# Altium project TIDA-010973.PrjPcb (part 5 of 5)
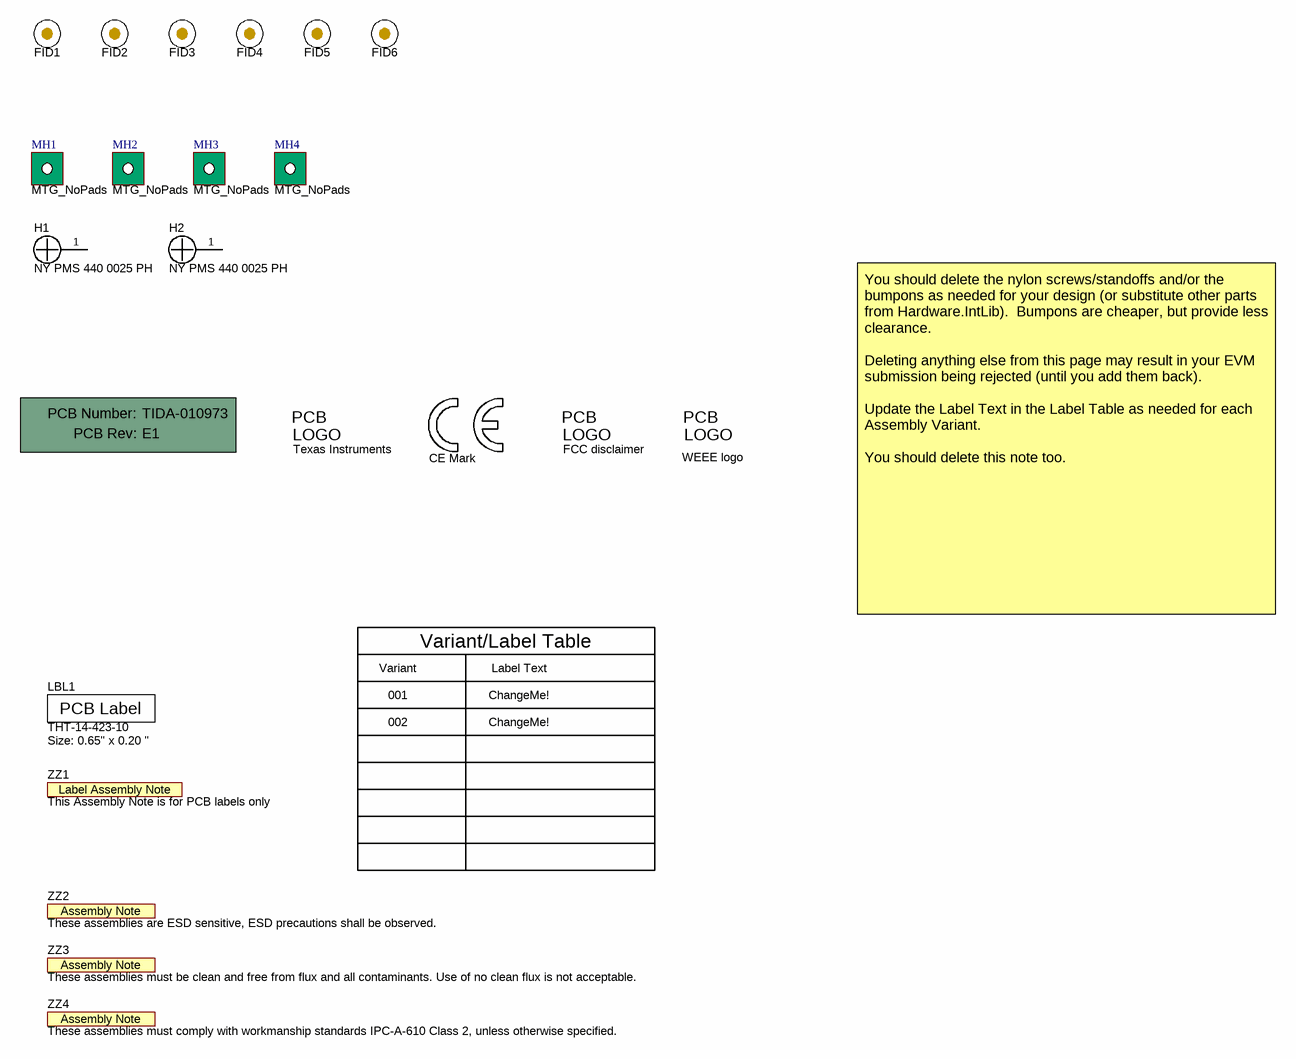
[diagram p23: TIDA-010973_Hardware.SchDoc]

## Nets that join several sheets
5V: TIDA-010973_HostPortInterface (J11.2 J11.4), TIDA-010973_SOM_PMIC (10 pins), TIDA-010973_SystemPower (16 pins), TIDA-010973_USB2 (C135.2 C136.1 U38.5)
GND: TIDA-010973_EthernetConnector (16 pins), TIDA-010973_HostPortInterface (49 pins), TIDA-010973_SOM-Memory (15 pins), SOM/SOM-ETH1 (21 pins), TIDA-010973_SOM_PMIC (159 pins), TIDA-010973_SOM_MCU (64 pins), SOM/SOM-ETH2 (21 pins), TIDA-010973_SystemPower (37 pins), TIDA-010973_SystemLED (38 pins), TIDA-010973_USB2 (40 pins), TIDA-010973_JTAG_UART (17 pins), TIDA-010973_Memory (9 pins), TIDA-010973_BootConfig (22 pins)
VDDA_AM261_1V8_LDO: TIDA-010973_SOM_PMIC (10 pins), TIDA-010973_SOM_MCU (C216.1 C217.2 U2.U15)
VSYS_1V8: TIDA-010973_HostPortInterface (C218.2 J12.3 U55.1 U55.5), TIDA-010973_SOM-Memory (19 pins), TIDA-010973_SOM_PMIC (11 pins), TIDA-010973_SOM_MCU (7 pins), TIDA-010973_Memory (18 pins)
VSYS_3V3: TIDA-010973_EthernetConnector (R84.2 R85.2 R86.2 R87.2), TIDA-010973_HostPortInterface (29 pins), TIDA-010973_SOM-Memory (C86.1 R55.2 U11.8), SOM/SOM-ETH1 (12 pins), TIDA-010973_SOM_PMIC (37 pins), TIDA-010973_SOM_MCU (29 pins), SOM/SOM-ETH2 (12 pins), TIDA-010973_SystemLED (34 pins), TIDA-010973_USB2 (R133.2 R141.1 U34.3), TIDA-010973_JTAG_UART (14 pins), TIDA-010973_BootConfig (19 pins)
VSYS_USB_5V: TIDA-010973_SystemPower (7 pins), TIDA-010973_USB2 (C131.2 C133.1 U37.7 U37.8)
~{ETH0_PHY_INT}: SOM/SOM-ETH1 (R27_SOM-ETH1.2 U9_SOM-ETH1.21), TIDA-010973_SOM_MCU (U2.B4)
~{ETH1_PHY_INT}: TIDA-010973_SOM_MCU (U2.A10), SOM/SOM-ETH2 (R27_SOM-ETH2.2 U9_SOM-ETH2.21)
~{PHY_RESET}: SOM/SOM-ETH1 (U9_SOM-ETH1.32), TIDA-010973_SOM_MCU (U3.7)
~{PHY_RESET}: TIDA-010973_SOM_MCU (U3.3), SOM/SOM-ETH2 (U9_SOM-ETH2.32)
AM261_I2C0.SCL: TIDA-010973_SOM-Memory (U11.6), TIDA-010973_SOM_PMIC (U1.14), TIDA-010973_SOM_MCU (R219.1 U2.A15 U7.12 U8.4), TIDA-010973_SystemLED (U21.4)
AM261_I2C0.SDA: TIDA-010973_SOM-Memory (U11.5), TIDA-010973_SOM_PMIC (U1.13), TIDA-010973_SOM_MCU (R17.1 U2.B15 U7.13 U8.3), TIDA-010973_SystemLED (U21.5)
AM261_PORZN: TIDA-010973_SOM_MCU (6 pins), TIDA-010973_BootConfig (R122.1)
AM261_SAFETY_ERR: TIDA-010973_SOM_MCU (U2.E3), TIDA-010973_SystemLED (Q13.1 R213.1)
AM261_SOP0: TIDA-010973_SOM_MCU (R16.1), TIDA-010973_BootConfig (U32.15)
AM261_SOP1: TIDA-010973_SOM_MCU (R120.1), TIDA-010973_BootConfig (U32.14)
AM261_SOP2: TIDA-010973_SOM_MCU (R121.1), TIDA-010973_BootConfig (U32.13)
AM261_SOP3: TIDA-010973_SOM_MCU (R123.1), TIDA-010973_BootConfig (U32.12)
AM261_TCK: TIDA-010973_SOM_MCU (U2.D4), TIDA-010973_JTAG_UART (R239.1 U51.2)
AM261_TDI: TIDA-010973_SOM_MCU (U2.C5), TIDA-010973_JTAG_UART (R240.1 U51.5)
AM261_TDO: TIDA-010973_SOM_MCU (R212.1), TIDA-010973_JTAG_UART (R241.1 U51.7)
AM261_TMS: TIDA-010973_SOM_MCU (U2.D6), TIDA-010973_JTAG_UART (R242.1 U51.10)
AM261_UART0_RXD: TIDA-010973_SOM_MCU (U2.A8), TIDA-010973_JTAG_UART (R226.1)
AM261_UART0_TXD: TIDA-010973_SOM_MCU (R218.1), TIDA-010973_JTAG_UART (U43.3)
AM261_USB0_D_N: TIDA-010973_SOM_MCU (U2.W1), TIDA-010973_USB2 (U34.8)
AM261_USB0_D_P: TIDA-010973_SOM_MCU (U2.V1), TIDA-010973_USB2 (U34.10)
AM261_USB0_DRVVBUS: TIDA-010973_SOM_MCU (U2.U2), TIDA-010973_USB2 (R142.1 U38.4)
AM261_USB0_MUX_SEL: TIDA-010973_SOM_MCU (U7.8), TIDA-010973_USB2 (R134.1 U34.11)
AM261_USB0_VBUS_OC: TIDA-010973_SOM_MCU (U2.F2), TIDA-010973_USB2 (R141.2 U38.3)
AM261_WARMRSTN: TIDA-010973_SOM_MCU (U2.G3 U4.2 U29.2 U47.2), TIDA-010973_BootConfig (Q14.1 R214.1 R215.2)
CLK_25M: SOM/SOM-ETH1 (U9_SOM-ETH1.9), TIDA-010973_SOM_MCU (R19.2)
CLK_25M: TIDA-010973_SOM_MCU (R18.2), SOM/SOM-ETH2 (U9_SOM-ETH2.9)
COL: SOM/SOM-ETH1 (U9_SOM-ETH1.28), TIDA-010973_SOM_MCU (U2.J19)
COL: TIDA-010973_SOM_MCU (U2.E20), SOM/SOM-ETH2 (U9_SOM-ETH2.28)
CRS: SOM/SOM-ETH1 (R30_SOM-ETH1.2 U9_SOM-ETH1.29), TIDA-010973_SOM_MCU (U2.J20)
CRS: TIDA-010973_SOM_MCU (U2.E19), SOM/SOM-ETH2 (R30_SOM-ETH2.2 U9_SOM-ETH2.29)
ETH0_LED_ACT: TIDA-010973_EthernetConnector (Q7.1), SOM/SOM-ETH1 (R29_SOM-ETH1.2 U9_SOM-ETH1.30)
ETH0_LED_LINK: TIDA-010973_EthernetConnector (Q5.1), SOM/SOM-ETH1 (R28_SOM-ETH1.1 R201_SOM-ETH1.2 U9_SOM-ETH1.31), TIDA-010973_SOM_MCU (U2.J18)
ETH0_RD_N: TIDA-010973_EthernetConnector (J2.3 U17.5), SOM/SOM-ETH1 (C78_SOM-ETH1.1 U9_SOM-ETH1.4)
ETH0_RD_P: TIDA-010973_EthernetConnector (J2.5 U17.1), SOM/SOM-ETH1 (C77_SOM-ETH1.1 U9_SOM-ETH1.5)
ETH0_TD_N: TIDA-010973_EthernetConnector (J2.6 U17.3), SOM/SOM-ETH1 (C80_SOM-ETH1.1 U9_SOM-ETH1.6)
ETH0_TD_P: TIDA-010973_EthernetConnector (J2.8 U17.4), SOM/SOM-ETH1 (C79_SOM-ETH1.1 U9_SOM-ETH1.7)
ETH1_LED_ACT: TIDA-010973_EthernetConnector (Q8.1), SOM/SOM-ETH2 (R29_SOM-ETH2.2 U9_SOM-ETH2.30)
ETH1_LED_LINK: TIDA-010973_EthernetConnector (Q6.1), TIDA-010973_SOM_MCU (U2.G18), SOM/SOM-ETH2 (R28_SOM-ETH2.1 R201_SOM-ETH2.2 U9_SOM-ETH2.31)
ETH1_RD_N: TIDA-010973_EthernetConnector (J3.3 U57.5), SOM/SOM-ETH2 (C78_SOM-ETH2.1 U9_SOM-ETH2.4)
ETH1_RD_P: TIDA-010973_EthernetConnector (J3.5 U57.1), SOM/SOM-ETH2 (C77_SOM-ETH2.1 U9_SOM-ETH2.5)
ETH1_TD_N: TIDA-010973_EthernetConnector (J3.6 U57.3), SOM/SOM-ETH2 (C80_SOM-ETH2.1 U9_SOM-ETH2.6)
ETH1_TD_P: TIDA-010973_EthernetConnector (J3.8 U57.4), SOM/SOM-ETH2 (C79_SOM-ETH2.1 U9_SOM-ETH2.7)
HPI_IRQ0: TIDA-010973_HostPortInterface (J11.26), TIDA-010973_SOM_MCU (U2.T1)
HPI_IRQ1: TIDA-010973_HostPortInterface (J11.27), TIDA-010973_SOM_MCU (U2.U1)
HPI_IRQ2: TIDA-010973_HostPortInterface (J11.28), TIDA-010973_SOM_MCU (U2.B10)
HPI_IRQ3: TIDA-010973_HostPortInterface (J11.49), TIDA-010973_SOM_MCU (U2.C19)
HPI_RESET: TIDA-010973_HostPortInterface (J11.58 U50.3 U54.2), TIDA-010973_SOM_MCU (U47.4)
MDC: SOM/SOM-ETH1 (R233_SOM-ETH1.2 U9_SOM-ETH1.12), TIDA-010973_SOM_MCU (U5.6), SOM/SOM-ETH2 (R233_SOM-ETH2.2 U9_SOM-ETH2.12)
MDIO: SOM/SOM-ETH1 (R23_SOM-ETH1.2 U9_SOM-ETH1.11), TIDA-010973_SOM_MCU (U5.10), SOM/SOM-ETH2 (R23_SOM-ETH2.2 U9_SOM-ETH2.11)
MMC0_CD: TIDA-010973_HostPortInterface (J6.9 R221.1), TIDA-010973_SOM_MCU (U2.A7)
MMC0_CLK: TIDA-010973_HostPortInterface (U52.2), TIDA-010973_SOM_MCU (R183.2)
MMC0_CMD: TIDA-010973_HostPortInterface (U52.5), TIDA-010973_SOM_MCU (R227.2)
MMC0_D0: TIDA-010973_HostPortInterface (U49.2), TIDA-010973_SOM_MCU (R228.2)
MMC0_D1: TIDA-010973_HostPortInterface (U49.5), TIDA-010973_SOM_MCU (R229.2)
MMC0_D2: TIDA-010973_HostPortInterface (U49.7), TIDA-010973_SOM_MCU (R230.2)
MMC0_D3: TIDA-010973_HostPortInterface (U49.10), TIDA-010973_SOM_MCU (R231.2)
MRn_CLK: SOM/SOM-ETH1 (R206_SOM-ETH1.1 R207_SOM-ETH1.2 U9_SOM-ETH1.19), TIDA-010973_SOM_MCU (U2.N20)
MRn_CLK: TIDA-010973_SOM_MCU (U2.F19), SOM/SOM-ETH2 (R206_SOM-ETH2.1 R207_SOM-ETH2.2 U9_SOM-ETH2.19)
MTn_CLK: SOM/SOM-ETH1 (U9_SOM-ETH1.22), TIDA-010973_SOM_MCU (U2.B20)
MTn_CLK: TIDA-010973_SOM_MCU (U2.M19), SOM/SOM-ETH2 (U9_SOM-ETH2.22)
OSPI0_CLK: TIDA-010973_SOM-Memory (R36.1 R52.2 U10.B2), TIDA-010973_SOM_MCU (R184.1)
OSPI0_CSN0: TIDA-010973_SOM-Memory (R34.1 U10.C2), TIDA-010973_SOM_MCU (U2.L2)
OSPI0_D0: TIDA-010973_SOM-Memory (R37.1 R45.2), TIDA-010973_SOM_MCU (U2.M3)
OSPI0_D1: TIDA-010973_SOM-Memory (R38.1 R46.2), TIDA-010973_SOM_MCU (U2.M2)
OSPI0_D2: TIDA-010973_SOM-Memory (R39.1 R47.2), TIDA-010973_SOM_MCU (U2.P1)
OSPI0_D3: TIDA-010973_SOM-Memory (R40.1 R48.2), TIDA-010973_SOM_MCU (U2.L1)
OSPI0_D4: TIDA-010973_SOM-Memory (R41.1 R49.2), TIDA-010973_SOM_MCU (U2.R4)
OSPI0_D5: TIDA-010973_SOM-Memory (R42.1 R50.2), TIDA-010973_SOM_MCU (U2.K1)
OSPI0_D6: TIDA-010973_SOM-Memory (R43.1 R53.2), TIDA-010973_SOM_MCU (U2.P2)
OSPI0_D7: TIDA-010973_SOM-Memory (R44.1 R54.2), TIDA-010973_SOM_MCU (U2.L4)
OSPI0_DQS: TIDA-010973_SOM-Memory (R33.1 R51.2 U10.C3), TIDA-010973_SOM_MCU (R182.1)
OSPI0_ECC_FAIL: TIDA-010973_SOM-Memory (R35.1 U10.A5), TIDA-010973_SOM_MCU (U2.J3)
OSPI0_RSTN: TIDA-010973_SOM-Memory (U10.A4), TIDA-010973_SOM_MCU (R193.2 U29.4)
OSPI1_CLK: TIDA-010973_SOM_MCU (R185.1), TIDA-010973_Memory (R189.1 R191.2 U16.B2)
OSPI1_CSN0: TIDA-010973_SOM_MCU (U2.V20), TIDA-010973_Memory (R83.1 R188.1 U16.A3)
OSPI1_D0: TIDA-010973_SOM_MCU (U2.V19), TIDA-010973_Memory (R66.1 R74.1)
OSPI1_D1: TIDA-010973_SOM_MCU (U2.Y18), TIDA-010973_Memory (R67.1 R75.1)
OSPI1_D2: TIDA-010973_SOM_MCU (U2.W18), TIDA-010973_Memory (R68.1 R76.1)
OSPI1_D3: TIDA-010973_SOM_MCU (U2.Y19), TIDA-010973_Memory (R69.1 R77.1)
OSPI1_D4: TIDA-010973_SOM_MCU (U2.W19), TIDA-010973_Memory (R70.1 R78.1)
OSPI1_D5: TIDA-010973_SOM_MCU (U2.U20), TIDA-010973_Memory (R71.1 R79.1)
OSPI1_D6: TIDA-010973_SOM_MCU (U2.T20), TIDA-010973_Memory (R72.1 R80.1)
OSPI1_D7: TIDA-010973_SOM_MCU (U2.V18), TIDA-010973_Memory (R73.1 R81.1)
OSPI1_DQS: TIDA-010973_SOM_MCU (R232.1), TIDA-010973_Memory (R82.1 R187.1 R190.2)
OSPI1_RSTN: TIDA-010973_SOM_MCU (R10.2 U4.4), TIDA-010973_Memory (U16.A4)
PMIC_NRST: TIDA-010973_SOM_PMIC (R202.2 U1.17), TIDA-010973_SOM_MCU (U31.1)
PORZ_PB: TIDA-010973_SOM_MCU (U31.2), TIDA-010973_BootConfig (U48.6)
PR0_IEP0_EDC_LATCH_IN0: TIDA-010973_HostPortInterface (J8.3 J11.53), TIDA-010973_SOM_MCU (U2.A14)
PR0_IEP0_EDC_LATCH_IN1: TIDA-010973_HostPortInterface (J8.4 J11.54), TIDA-010973_SOM_MCU (U2.B19)
PR0_IEP0_EDC_SYNC_OUT0: TIDA-010973_HostPortInterface (J8.1 J11.51), TIDA-010973_SOM_MCU (U2.C18)
PR0_IEP0_EDC_SYNC_OUT1: TIDA-010973_HostPortInterface (U55.3), TIDA-010973_SOM_MCU (U2.T19)
PR0_MII0_RXD0: SOM/SOM-ETH1 (U9_SOM-ETH1.16), TIDA-010973_SOM_MCU (U2.N17)
PR0_MII0_RXD1: SOM/SOM-ETH1 (U9_SOM-ETH1.15), TIDA-010973_SOM_MCU (U2.N19)
PR0_MII0_RXD2: SOM/SOM-ETH1 (R32_SOM-ETH1.2 R204_SOM-ETH1.1 U9_SOM-ETH1.14), TIDA-010973_SOM_MCU (U2.M18)
PR0_MII0_RXD3: SOM/SOM-ETH1 (R31_SOM-ETH1.2 R205_SOM-ETH1.1 U9_SOM-ETH1.13), TIDA-010973_SOM_MCU (U2.M20)
PR0_MII0_RXDV: SOM/SOM-ETH1 (U9_SOM-ETH1.18), TIDA-010973_SOM_MCU (U2.L20)
PR0_MII0_RXER: SOM/SOM-ETH1 (U9_SOM-ETH1.20), TIDA-010973_SOM_MCU (U2.K19)
PR0_MII0_TXD0: SOM/SOM-ETH1 (U9_SOM-ETH1.24), TIDA-010973_SOM_MCU (R234.2)
PR0_MII0_TXD1: SOM/SOM-ETH1 (U9_SOM-ETH1.25), TIDA-010973_SOM_MCU (R235.2)
PR0_MII0_TXD2: SOM/SOM-ETH1 (U9_SOM-ETH1.26), TIDA-010973_SOM_MCU (R236.2)
PR0_MII0_TXD3: SOM/SOM-ETH1 (U9_SOM-ETH1.27), TIDA-010973_SOM_MCU (R237.2)
PR0_MII0_TXEN: SOM/SOM-ETH1 (U9_SOM-ETH1.23), TIDA-010973_SOM_MCU (U2.E18)
PR0_MII1_RXD0: TIDA-010973_SOM_MCU (U2.H20), SOM/SOM-ETH2 (U9_SOM-ETH2.16)
PR0_MII1_RXD1: TIDA-010973_SOM_MCU (U2.H19), SOM/SOM-ETH2 (U9_SOM-ETH2.15)
PR0_MII1_RXD2: TIDA-010973_SOM_MCU (U2.H17), SOM/SOM-ETH2 (R32_SOM-ETH2.2 R204_SOM-ETH2.1 U9_SOM-ETH2.14)
PR0_MII1_RXD3: TIDA-010973_SOM_MCU (U2.G20), SOM/SOM-ETH2 (R31_SOM-ETH2.2 R205_SOM-ETH2.1 U9_SOM-ETH2.13)
PR0_MII1_RXDV: TIDA-010973_SOM_MCU (U2.G19), SOM/SOM-ETH2 (U9_SOM-ETH2.18)
PR0_MII1_RXER: TIDA-010973_SOM_MCU (U2.F20), SOM/SOM-ETH2 (U9_SOM-ETH2.20)
PR0_MII1_TXD0: TIDA-010973_SOM_MCU (R208.2), SOM/SOM-ETH2 (U9_SOM-ETH2.24)
PR0_MII1_TXD1: TIDA-010973_SOM_MCU (R209.2), SOM/SOM-ETH2 (U9_SOM-ETH2.25)
PR0_MII1_TXD2: TIDA-010973_SOM_MCU (R210.2), SOM/SOM-ETH2 (U9_SOM-ETH2.26)
PR0_MII1_TXD3: TIDA-010973_SOM_MCU (R211.2), SOM/SOM-ETH2 (U9_SOM-ETH2.27)
PR0_MII1_TXEN: TIDA-010973_SOM_MCU (U2.P18), SOM/SOM-ETH2 (U9_SOM-ETH2.23)
PR1_MDIO0_MDC: TIDA-010973_HostPortInterface (J11.56), TIDA-010973_SOM_MCU (U2.A18)
PR1_MDIO0_MDIO: TIDA-010973_HostPortInterface (J11.55), TIDA-010973_SOM_MCU (U2.A17)
PR1_PRU0_GPIO0: TIDA-010973_HostPortInterface (U26.2), TIDA-010973_SOM_MCU (R123.2 U2.B12)
PR1_PRU0_GPIO1: TIDA-010973_HostPortInterface (U26.5), TIDA-010973_SOM_MCU (U2.C12)
PR1_PRU0_GPIO2: TIDA-010973_HostPortInterface (J11.7), TIDA-010973_SOM_MCU (U2.B13)
PR1_PRU0_GPIO3: TIDA-010973_HostPortInterface (J11.8), TIDA-010973_SOM_MCU (U2.B1)
PR1_PRU0_GPIO4: TIDA-010973_HostPortInterface (J11.9), TIDA-010973_SOM_MCU (U2.A3)
PR1_PRU0_GPIO5: TIDA-010973_HostPortInterface (J11.10), TIDA-010973_SOM_MCU (U2.B3)
PR1_PRU0_GPIO6: TIDA-010973_HostPortInterface (J11.11), TIDA-010973_SOM_MCU (U2.A2)
PR1_PRU0_GPIO7: TIDA-010973_HostPortInterface (J11.12), TIDA-010973_SOM_MCU (U2.D8)
PR1_PRU0_GPIO8: TIDA-010973_HostPortInterface (J11.13), TIDA-010973_SOM_MCU (U2.C3)
PR1_PRU0_GPIO9: TIDA-010973_HostPortInterface (U26.7), TIDA-010973_SOM_MCU (R121.2 U2.A13)
PR1_PRU0_GPIO10: TIDA-010973_HostPortInterface (J11.15), TIDA-010973_SOM_MCU (U2.A19)
PR1_PRU0_GPIO11: TIDA-010973_HostPortInterface (J11.16), TIDA-010973_SOM_MCU (U2.C2)
PR1_PRU0_GPIO12: TIDA-010973_HostPortInterface (J11.17), TIDA-010973_SOM_MCU (U2.D2)
PR1_PRU0_GPIO13: TIDA-010973_HostPortInterface (J11.18), TIDA-010973_SOM_MCU (U2.D1)
PR1_PRU0_GPIO14: TIDA-010973_HostPortInterface (J11.19), TIDA-010973_SOM_MCU (U2.E2)
PR1_PRU0_GPIO15: TIDA-010973_HostPortInterface (J11.20), TIDA-010973_SOM_MCU (U2.C1)
PR1_PRU0_GPIO16: TIDA-010973_HostPortInterface (J11.21), TIDA-010973_SOM_MCU (U2.B2)
PR1_PRU0_GPIO17: TIDA-010973_HostPortInterface (J11.22), TIDA-010973_SOM_MCU (R217.1 U2.B9), TIDA-010973_SystemLED (U21.6)
PR1_PRU0_GPIO18: TIDA-010973_HostPortInterface (J11.23), TIDA-010973_SOM_MCU (R13.1 U2.A9), TIDA-010973_SystemLED (U21.7)
PR1_PRU0_GPIO19: TIDA-010973_HostPortInterface (J11.24), TIDA-010973_SOM_MCU (U2.B16)
PR1_PRU0_GPIO20: TIDA-010973_HostPortInterface (J11.25), TIDA-010973_SOM_MCU (U2.C14)
PR1_PRU1_GPIO0: TIDA-010973_HostPortInterface (J11.29), TIDA-010973_SOM_MCU (U2.W16)
PR1_PRU1_GPIO1: TIDA-010973_HostPortInterface (J11.30), TIDA-010973_SOM_MCU (U2.Y16)
PR1_PRU1_GPIO2: TIDA-010973_HostPortInterface (J11.31), TIDA-010973_SOM_MCU (U2.W17)
PR1_PRU1_GPIO3: TIDA-010973_HostPortInterface (U27.2), TIDA-010973_SOM_MCU (U2.A12)
PR1_PRU1_GPIO4: TIDA-010973_HostPortInterface (J11.33), TIDA-010973_SOM_MCU (U2.D11)
PR1_PRU1_GPIO5: TIDA-010973_HostPortInterface (J11.34), TIDA-010973_SOM_MCU (U2.E1)
PR1_PRU1_GPIO6: TIDA-010973_HostPortInterface (J11.35), TIDA-010973_SOM_MCU (U2.A11)
PR1_PRU1_GPIO7: TIDA-010973_HostPortInterface (J11.36), TIDA-010973_SOM_MCU (U2.D15)
PR1_PRU1_GPIO8: TIDA-010973_HostPortInterface (J11.37), TIDA-010973_SOM_MCU (U2.B11)
PR1_PRU1_GPIO9: TIDA-010973_HostPortInterface (J11.38), TIDA-010973_SOM_MCU (U2.Y17)
PR1_PRU1_GPIO10: TIDA-010973_HostPortInterface (J11.39), TIDA-010973_SOM_MCU (U2.C16)
PR1_PRU1_GPIO11: TIDA-010973_HostPortInterface (J11.40), TIDA-010973_SOM_MCU (R16.2 U2.R2)
PR1_PRU1_GPIO12: TIDA-010973_HostPortInterface (J11.41), TIDA-010973_SOM_MCU (R120.2 U2.R1)
PR1_PRU1_GPIO13: TIDA-010973_HostPortInterface (J11.42), TIDA-010973_SOM_MCU (U2.B17)
PR1_PRU1_GPIO14: TIDA-010973_HostPortInterface (U28.2), TIDA-010973_SOM_MCU (U2.B18)
PR1_PRU1_GPIO15: TIDA-010973_HostPortInterface (U27.5), TIDA-010973_SOM_MCU (U2.C9)
PR1_PRU1_GPIO16: TIDA-010973_HostPortInterface (U27.7), TIDA-010973_SOM_MCU (U2.D10)
PR1_PRU1_GPIO17: TIDA-010973_HostPortInterface (U28.5), TIDA-010973_SOM_MCU (R238.2)
PR1_PRU1_GPIO18: TIDA-010973_HostPortInterface (U28.7), TIDA-010973_SOM_MCU (U2.A16)
PR1_PRU1_GPIO19: TIDA-010973_HostPortInterface (U28.10), TIDA-010973_SOM_MCU (U2.C7)
SEL_HPI_FSI: TIDA-010973_HostPortInterface (R118.2 U26.15 U27.15), TIDA-010973_SOM_MCU (U7.9)
SEL_HPI_SPI: TIDA-010973_HostPortInterface (R119.2 U28.15), TIDA-010973_SOM_MCU (U7.10)
UI_LED1_G: TIDA-010973_SOM_MCU (U2.T2), TIDA-010973_SystemLED (Q12.1)
UI_LED1_R: TIDA-010973_SOM_MCU (U2.U4), TIDA-010973_SystemLED (Q9.1)
UI_LED2_G: TIDA-010973_SOM_MCU (U2.J1), TIDA-010973_SystemLED (Q11.1)
UI_LED2_R: TIDA-010973_SOM_MCU (U2.J2), TIDA-010973_SystemLED (Q10.1)
USER_INT: TIDA-010973_SOM_MCU (U2.B14), TIDA-010973_SystemLED (R105.2 U23.11)

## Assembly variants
001: not fitted C? C? R23_SOM-ETH2 R25_SOM-ETH1 R25_SOM-ETH2 R30_SOM-ETH1 R33 R36 R55 R83 R158 R159 R160 R161 R196 R199 R200 R? R? R? R? R? R? R? R?_SOM-ETH1 R?_SOM-ETH1 R?_SOM-ETH1 R?_SOM-ETH1 R?_SOM-ETH1 R?_SOM-ETH2 R?_SOM-ETH2 R?_SOM-ETH2 R?_SOM-ETH2 R?_SOM-ETH2 R?_SOM-ETH2 SH-J1 TP31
